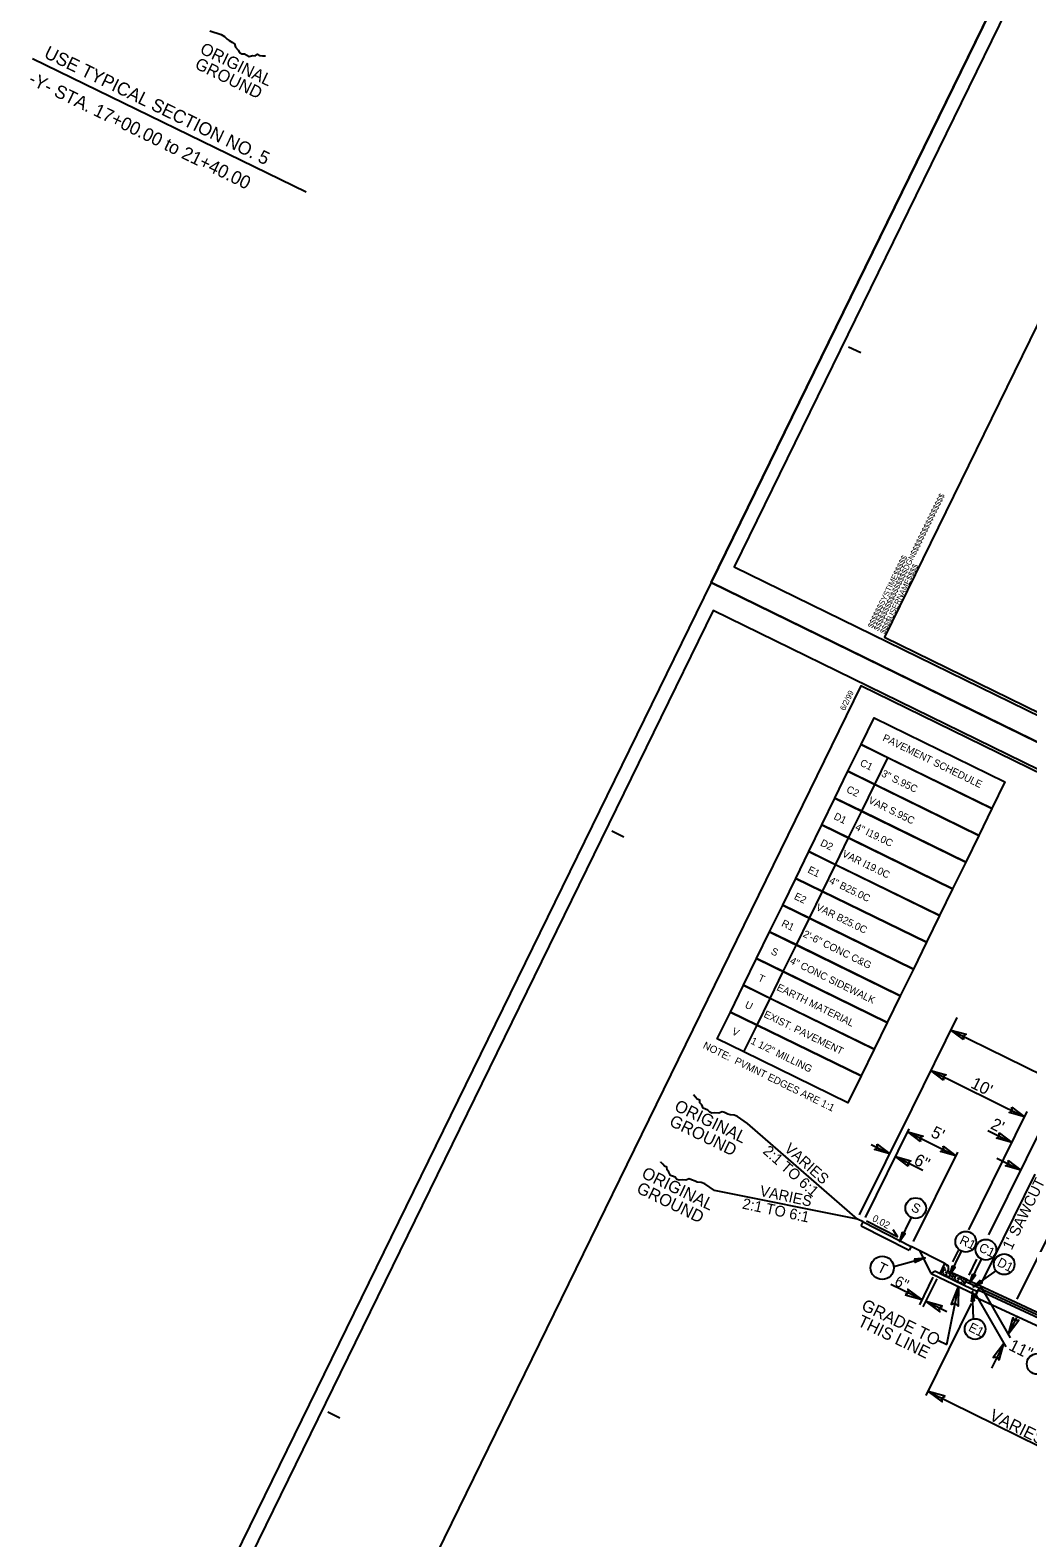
# Model space of a CAD drawing. Extents: x 1518247 to 1523638, y 635234 to 639927.
# Drawn here: x 1519327 to 1520253, y 636076 to 637475 of the extents above; entities that cross this region are included whole.
import ezdxf

# ---------------------------------------------------------------- set-up
doc = ezdxf.new("R2010")
doc.units = 0
for name, color, linetype in [('Default', 7, 'Continuous'), ('DTM TIN Hull White', 7, 'Continuous'), ('Old_Level_21', 7, 'Continuous'), ('Prop Dimension', 7, 'Continuous'), ('Prop Pavement Schedule Description CELL', 7, 'Continuous'), ('Prop Shade Light', 7, 'Continuous'), ('Sheet Cutting Line CELL', 7, 'Continuous'), ('Sheet Plot Border Inside CELL', 7, 'Continuous'), ('Sheet Plot Border Outside CELL', 7, 'Continuous'), ('Sheet Typical CELL', 7, 'Continuous'), ('Typical Berm CELL', 7, 'Continuous'), ('Typical Berm Information CELL', 7, 'Continuous'), ('Typical Curb CELL', 7, 'Continuous'), ('Typical Hinge Slope Arterial CELL', 7, 'Continuous'), ('Typical Hinge Slope Interstate CELL', 7, 'Continuous'), ('Typical ID Circle CELL', 7, 'Continuous'), ('Typical Pavement Slope CELL', 7, 'Continuous'), ('Typical Pavement Slope Information CELL', 7, 'Continuous'), ('Typical Shoulder Slope CELL', 7, 'Continuous'), ('Typical Text General CELL', 7, 'Continuous'), ('Typical Text ID Circle CELL', 7, 'Continuous'), ('Typical Text Label CELL', 7, 'Continuous')]:
    doc.layers.add(name, color=color, linetype=linetype)

# ---------------------------------------------------------------- blocks, each defined once
blk = doc.blocks.new('TERMINATOR')
at = {"layer": 'Prop Shade Light'}
blk.add_lwpolyline([(-0.469, 0.081), (0, 0), (-0.471, -0.083), (-0.411, 0)], close=True, dxfattribs=at)

msp = doc.modelspace()

# ---------------------------------------------------------------- linework, layer by layer
at = {"layer": 'Default'}
msp.add_lwpolyline([(1521471.5, 636222.3), (1519958.7, 636962.2), (1520442, 637950.3), (1521954.7, 637210.5)], close=True, dxfattribs=at)
at = {"layer": 'DTM TIN Hull White'}
for p, q in [((1520203.4, 636299.5), (1520206.5, 636306.1)), ((1520206.5, 636306.1), (1520445.2, 636195.2)), ((1520203.4, 636299.5), (1520442.1, 636188.9))]:
    msp.add_line(p, q, dxfattribs=at)
at = {"layer": 'Prop Dimension'}
for p, q in [((1520145.1, 636474), (1520186.9, 636558.6)), ((1520181.2, 636547), (1521070.1, 636107.9)), ((1520162.6, 636509.4), (1520249.4, 636466.5)), ((1520096.5, 636375.6), (1520145.1, 636474)), ((1520197.8, 636361.6), (1520252, 636471.5)), ((1520101.8, 636373), (1520142.5, 636455.5)), ((1520215.6, 636453.7), (1520237.8, 636442.7)), ((1520216.5, 636356.9), (1520269, 636463.2)), ((1520107.1, 636440.8), (1520124.5, 636432.2)), ((1520141.1, 636452.6), (1520185.9, 636430.4)), ((1520242.8, 636297.4), (1520313.8, 636441)), ((1520129.7, 636429.6), (1520155.1, 636417.1)), ((1520146.6, 636350.9), (1520187.5, 636433.8)), ((1520223.7, 636428.2), (1520246.2, 636417.1)), ((1520210.1, 636313.5), (1520259.5, 636413.3)), ((1520183, 636331.9), (1520188.3, 636342.5)), ((1520198, 636319.5), (1520205.4, 636334.5)), ((1520164.5, 636317.9), (1520151.9, 636292.1)), ((1520168, 636316.1), (1520155.3, 636290.2)), ((1520154.3, 636297), (1520125.6, 636311)), ((1520177.3, 636255.2), (1520188.3, 636309)), ((1520204.2, 636301.4), (1520232.2, 636253)), ((1520208.4, 636309.9), (1520236.3, 636261.5)), ((1520177.5, 636285.7), (1520157.8, 636295.3)), ((1520158.3, 636208.1), (1520200.4, 636293.2)), ((1520242.1, 636280.5), (1520234.4, 636264.8)), ((1520169.6, 636259.1), (1520177.3, 636255.2)), ((1520230.2, 636256.3), (1520219, 636233.3)), ((1520160.2, 636211.8), (1520395.9, 636095.4))]:
    msp.add_line(p, q, dxfattribs=at)
at = {"layer": 'Prop Pavement Schedule Description CELL'}
for points in [[(1520122.7, 636799.6), (1520097.9, 636811.8), (1520110, 636836.6), (1520231.3, 636777.3), (1520219.2, 636752.4), (1520122.7, 636799.6)], [(1520110.6, 636774.8), (1520085.7, 636787), (1520097.9, 636811.8), (1520219.2, 636752.4), (1520207, 636727.6), (1520110.6, 636774.8), (1520122.7, 636799.6)], [(1520098.4, 636750), (1520073.6, 636762.1), (1520085.7, 636787), (1520207, 636727.6), (1520194.9, 636702.8), (1520098.4, 636750), (1520110.6, 636774.8)], [(1520086.3, 636725.2), (1520061.5, 636737.3), (1520073.6, 636762.1), (1520194.9, 636702.8), (1520182.8, 636678), (1520086.3, 636725.2), (1520098.4, 636750)], [(1520074.2, 636700.4), (1520049.4, 636712.5), (1520061.5, 636737.3), (1520182.8, 636678), (1520170.6, 636653.2), (1520074.2, 636700.4), (1520086.3, 636725.2)], [(1520062, 636675.6), (1520037.2, 636687.7), (1520049.4, 636712.5), (1520170.6, 636653.2), (1520158.5, 636628.4), (1520062, 636675.6), (1520074.2, 636700.4)], [(1520049.9, 636650.8), (1520025.1, 636662.9), (1520037.2, 636687.7), (1520158.5, 636628.4), (1520146.4, 636603.6), (1520049.9, 636650.8), (1520062, 636675.6)], [(1520037.8, 636626), (1520013, 636638.1), (1520025.1, 636662.9), (1520146.4, 636603.6), (1520134.2, 636578.8), (1520037.8, 636626), (1520049.9, 636650.8)], [(1520025.6, 636601.2), (1520000.8, 636613.3), (1520013, 636638.1), (1520134.2, 636578.8), (1520122.1, 636554), (1520025.6, 636601.2), (1520037.8, 636626)], [(1520013.5, 636576.4), (1519988.7, 636588.5), (1520000.8, 636613.3), (1520122.1, 636554), (1520110, 636529.2), (1520013.5, 636576.4), (1520025.6, 636601.2)], [(1520001.4, 636551.6), (1519976.6, 636563.7), (1519988.7, 636588.5), (1520110, 636529.2), (1520097.8, 636504.4), (1520001.4, 636551.6), (1520013.5, 636576.4)], [(1519989.2, 636526.8), (1519964.4, 636538.9), (1519976.6, 636563.7), (1520097.8, 636504.4), (1520085.7, 636479.6), (1519989.2, 636526.8), (1520001.4, 636551.6)]]:
    msp.add_lwpolyline(points, dxfattribs=at)
at = {"layer": 'Prop Shade Light'}
for points in [[(1520136, 636359.6), (1520133.4, 636350.9), (1520138.8, 636358.3), (1520136.9, 636358)], [(1520147.2, 636334.8), (1520157.3, 636335.7), (1520148.1, 636331.4), (1520148.9, 636333.5)], [(1520182.5, 636328.4), (1520180, 636319.7), (1520185.3, 636327), (1520183.4, 636326.7)], [(1520201.1, 636321), (1520198.6, 636312.3), (1520203.9, 636319.7), (1520202, 636319.3)], [(1520208.3, 636315.1), (1520201.9, 636308.8), (1520210.2, 636312.6), (1520208.3, 636313.3)], [(1520203, 636295.6), (1520201.1, 636304.4), (1520199.9, 636295.4), (1520201.4, 636296.6)]]:
    msp.add_lwpolyline(points, close=True, dxfattribs=at)
at = {"layer": 'Sheet Cutting Line CELL'}
for p, q in [((1520442, 637950.3), (1519958.7, 636962.2)), ((1519958.7, 636962.2), (1519475.4, 635974)), ((1519958.7, 636962.2), (1521471.5, 636222.3)), ((1521471.5, 636222.3), (1519958.7, 636962.2))]:
    msp.add_line(p, q, dxfattribs=at)
at = {"layer": 'Sheet Plot Border Inside CELL'}
for points in [[(1521940.8, 637192.3), (1520443.8, 637924.5), (1519980.2, 636976.6), (1521477.3, 636244.5)], [(1521457.5, 636204.1), (1519960.5, 636936.3), (1519496.9, 635988.5), (1520994, 635256.3)]]:
    msp.add_lwpolyline(points, close=True, dxfattribs=at)
at = {"layer": 'Sheet Plot Border Outside CELL'}
for points in [[(1521954.7, 637210.5), (1520442, 637950.3), (1519958.7, 636962.2), (1521471.5, 636222.3)], [(1521471.5, 636222.3), (1519958.7, 636962.2), (1519475.4, 635974), (1520988.2, 635234.2)]]:
    msp.add_lwpolyline(points, close=True, dxfattribs=at)
at = {"layer": 'Sheet Typical CELL'}
for p, q in [((1520086.2, 637180.9), (1520097.5, 637175.4)), ((1520119.7, 636911.3), (1520119.7, 636911.3)), ((1520119.7, 636911.3), (1520119.7, 636911.3)), ((1520119.7, 636911.3), (1520119.7, 636911.3)), ((1520119.7, 636911.3), (1520119.7, 636911.3)), ((1520119.7, 636911.3), (1520119.7, 636911.3)), ((1520119.7, 636911.3), (1520119.7, 636911.3)), ((1519866.6, 636731.7), (1519877.8, 636726.2)), ((1520098, 636365.5), (1520099.8, 636369.1)), ((1520098, 636365.5), (1520142.5, 636342.8)), ((1520099.8, 636369.1), (1520144.3, 636346.3)), ((1520144.3, 636346.3), (1520142.5, 636342.8)), ((1519603, 636192.7), (1519614.2, 636187.3))]:
    msp.add_line(p, q, dxfattribs=at)
for points in [[(1521928.5, 637195.5), (1520581, 637854.5), (1520119.7, 636911.3), (1521467.2, 636252.3)], [(1521445.2, 636207.3), (1520097.7, 636866.4), (1519636.4, 635923.1), (1520983.9, 635264.1)]]:
    msp.add_lwpolyline(points, close=True, dxfattribs=at)
msp.add_lwpolyline([(1520153.4, 636894.8), (1520153.4, 636894.8)], dxfattribs=at)
at = {"layer": 'Typical Berm CELL'}
for p, q in [((1520099.8, 636369.1), (1520094.6, 636371.7)), ((1520175.5, 636330.3), (1520144.3, 636346.3))]:
    msp.add_line(p, q, dxfattribs=at)
at = {"layer": 'Typical Curb CELL'}
for p, q in [((1520171.1, 636321.3), (1520175.5, 636330.3)), ((1520175.5, 636330.3), (1520177.8, 636329.2)), ((1520171.1, 636321.3), (1520193.5, 636310.3)), ((1520173.9, 636323.3), (1520172.6, 636323.1)), ((1520172.6, 636323.1), (1520173.9, 636322)), ((1520173.9, 636322), (1520173.9, 636323.3)), ((1520175.2, 636325.7), (1520174.1, 636326.8)), ((1520174.1, 636326.8), (1520175.7, 636326.5)), ((1520175.7, 636326.5), (1520175.2, 636325.7)), ((1520178.8, 636325.9), (1520178.9, 636326)), ((1520196.1, 636315.6), (1520180, 636322.6)), ((1520180.8, 636320.6), (1520180, 636319.7)), ((1520180, 636319.7), (1520181, 636319.1)), ((1520181, 636319.1), (1520180.8, 636320.6)), ((1520185.1, 636317.9), (1520183.8, 636317.6)), ((1520183.8, 636317.6), (1520185.1, 636316.5)), ((1520185.1, 636316.5), (1520185.1, 636317.9)), ((1520192, 636315.1), (1520191.2, 636314.2)), ((1520191.2, 636314.2), (1520192.2, 636313.6)), ((1520192.2, 636313.6), (1520192, 636315.1)), ((1520193.5, 636310.3), (1520196.1, 636315.6))]:
    msp.add_line(p, q, dxfattribs=at)
for centre in [(1520175.1, 636329.3), (1520177.2, 636328.6), (1520172.6, 636321.1), (1520174.3, 636320.7), (1520174.4, 636324.5), (1520174.8, 636327.4), (1520175.6, 636319.4), (1520175.7, 636324.4), (1520176.6, 636322.2), (1520176.6, 636320.1), (1520177.3, 636318.9), (1520177.6, 636321.4), (1520178.1, 636323), (1520178.2, 636323.6), (1520179.2, 636318.2), (1520179.3, 636321.5), (1520180, 636322.3), (1520180.3, 636316.9), (1520181.6, 636321.1), (1520181.8, 636318.7), (1520182.3, 636316.1), (1520182.5, 636317.9), (1520182.6, 636321), (1520183.2, 636319.8), (1520183.6, 636318.9), (1520183.8, 636315.6), (1520183.9, 636319.9), (1520185.5, 636315.2), (1520185.6, 636319), (1520186.8, 636313.9), (1520186.9, 636319), (1520187.8, 636316.7), (1520187.8, 636314.7), (1520188.8, 636315.9), (1520189.3, 636317.6), (1520189.4, 636318.1), (1520190.5, 636316), (1520191.2, 636316.8), (1520192.8, 636315.6), (1520192.8, 636316.7), (1520194, 636315.9), (1520194.5, 636314.3), (1520195.1, 636314.4), (1520188.5, 636313.4), (1520190.4, 636312.7), (1520191.6, 636311.4), (1520193, 636313.2), (1520193.5, 636310.7), (1520193.7, 636312.4), (1520194.9, 636313.4)]:
    msp.add_circle(centre, 0.0802, dxfattribs=at)
for centre, start, end in [((1520176.7, 636327), 333.9377, 63.9377), ((1520181, 636324.8), 153.9377, 246.3222)]:
    msp.add_arc(centre, 2.4, start, end, dxfattribs=at)
at = {"layer": 'Typical Hinge Slope Interstate CELL'}
for p, q in [((1520094.6, 636371.7), (1519992.3, 636460.3)), ((1520094.6, 636371.7), (1519961.9, 636398.1)), ((1520162.8, 636321.2), (1520152.8, 636342)), ((1520167, 636323.3), (1520162.8, 636321.2)), ((1520207.4, 636307.9), (1520204.3, 636301.4))]:
    msp.add_line(p, q, dxfattribs=at)
for points in [[(1519493.5, 637473.8), (1519504.1, 637470.5), (1519507.1, 637468.7), (1519509.5, 637466), (1519511.5, 637464.8), (1519514.5, 637463.1), (1519516.5, 637461.9), (1519517.4, 637458.7), (1519519.8, 637455.9), (1519521.2, 637453.8), (1519523.2, 637452.6), (1519525.8, 637452.4), (1519527.8, 637451.2), (1519529.9, 637450.1), (1519533, 637450.9), (1519535.6, 637450.7), (1519537.8, 637452.2), (1519539.8, 637451), (1519542.4, 637450.8), (1519545, 637450.7), (1519545.2, 637450.6)], [(1519992.3, 636460.3), (1519983.3, 636466.7), (1519980, 636468), (1519976.4, 636468.2), (1519974.2, 636469.1), (1519971, 636470.4), (1519968.8, 636471.2), (1519965.8, 636469.9), (1519962.1, 636470.1), (1519959.5, 636469.9), (1519957.4, 636470.8), (1519955.6, 636472.7), (1519953.5, 636473.6), (1519951.3, 636474.5), (1519950, 636477.5), (1519948.3, 636479.4), (1519948.1, 636482), (1519945.9, 636482.9), (1519944.2, 636484.8), (1519942.5, 636486.8), (1519942.4, 636486.9)], [(1519961.9, 636398.1), (1519952.8, 636404.4), (1519949.6, 636405.7), (1519945.9, 636405.9), (1519943.8, 636406.8), (1519940.5, 636408.1), (1519938.4, 636409), (1519935.3, 636407.7), (1519931.7, 636407.9), (1519929.1, 636407.7), (1519926.9, 636408.5), (1519925.2, 636410.5), (1519923, 636411.4), (1519920.9, 636412.2), (1519919.6, 636415.2), (1519917.9, 636417.2), (1519917.6, 636419.8), (1519915.5, 636420.7), (1519913.8, 636422.6), (1519912, 636424.5), (1519911.9, 636424.7)]]:
    msp.add_lwpolyline(points, dxfattribs=at)
at = {"layer": 'Typical ID Circle CELL'}
for p, q in [((1520144.3, 636373.2), (1520133.4, 636350.9)), ((1520190.8, 636342), (1520180, 636319.7)), ((1520128.3, 636327.8), (1520157.4, 636335.7)), ((1520209.4, 636334.6), (1520198.6, 636312.3)), ((1520223.1, 636323.8), (1520202, 636308.8)), ((1520202.2, 636279.1), (1520201.1, 636303.8))]:
    msp.add_line(p, q, dxfattribs=at)
for centre, radius in [((1520148.5, 636381.8), 9.59), ((1520195, 636350.6), 9.59), ((1520213.7, 636343.2), 9.59), ((1520117.5, 636326.4), 10.8), ((1520230.6, 636329.7), 9.59), ((1520203.6, 636269.6), 9.59), ((1520261.2, 636237.3), 9.59)]:
    msp.add_circle(centre, radius, dxfattribs=at)
at = {"layer": 'Typical Pavement Slope CELL'}
for p, q in [((1520167, 636323.3), (1520171.1, 636321.3)), ((1520196.1, 636315.6), (1520241.4, 636294.5)), ((1520207.3, 636307.9), (1520472.1, 636185)), ((1520241.4, 636294.5), (1520350.2, 636244))]:
    msp.add_line(p, q, dxfattribs=at)
at = {"layer": 'Typical Pavement Slope Information CELL'}
for q in [(1520103, 636369.8), (1520127.7, 636361.8)]:
    msp.add_line((1520132.1, 636354.9), q, dxfattribs=at)
at = {"layer": 'Typical Shoulder Slope CELL'}
for p, q in [((1520162.8, 636321.2), (1520204.3, 636301.4)), ((1520193.5, 636310.3), (1520205.8, 636304.6)), ((1520195, 636313.6), (1520207.3, 636307.9))]:
    msp.add_line(p, q, dxfattribs=at)
at = {"layer": 'Typical Text Label CELL'}
msp.add_line((1519328.9, 637448.2), (1519582.9, 637324.6), dxfattribs=at)

# ---------------------------------------------------------------- block references
at = {"layer": 'Prop Dimension'}
for p, xscale, yscale, rotation in [((1520181.2, 636547), 30.9388560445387, 33.305184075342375, 153.71146049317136), ((1520162.6, 636509.4), 30.9388560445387, 33.305184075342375, 153.71146049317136), ((1520249.5, 636466.5), 30.9388560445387, 33.305184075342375, -26.28853950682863), ((1520141.1, 636452.6), 30.9388560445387, 33.305184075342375, 153.71146049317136), ((1520124.5, 636432.2), 30.9388560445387, 33.305184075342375, -26.28853950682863), ((1520237.8, 636442.7), 30.9388560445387, 33.305184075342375, -26.28853950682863), ((1520129.7, 636429.6), 30.9388560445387, 33.305184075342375, 153.71146049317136), ((1520185.9, 636430.4), 30.9388560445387, 33.305184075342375, -26.28853950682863), ((1520246.2, 636417.1), 30.9388560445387, 33.305184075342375, -26.28853950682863), ((1520154.3, 636297), 33.82820784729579, -36.41552511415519, -26.020730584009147), ((1520188.3, 636309), 38.04253472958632, 40.95218065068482, 78.30414461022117), ((1520157.8, 636295.3), 33.82820784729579, -36.41552511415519, 153.97926941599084), ((1520234.4, 636264.8), 33.82820784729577, -36.415525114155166, -115.99597801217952), ((1520230.2, 636256.3), 33.82820784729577, -36.41552511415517, 64.0796934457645), ((1520160.2, 636211.8), 33.82820784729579, -36.41552511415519, 153.97926941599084)]:
    msp.add_blockref('TERMINATOR', p, dxfattribs=dict(at, xscale=xscale, yscale=yscale, rotation=rotation))

# ---------------------------------------------------------------- texts
at = {"layer": 'Old_Level_21'}
msp.add_text('NOTE:  PVMNT EDGES ARE 1:1', height=6.75, rotation=333.8298, dxfattribs=at).set_placement((1519950.5, 636530.5))
at = {"layer": 'Prop Dimension'}
for s, height, rotation, p in [("10'", 11.19, 333.7115, (1520198.8, 636493.9)), ("5'", 11.19, 333.7115, (1520161.7, 636448.5)), ("2'", 11.19, 333.7115, (1520217.1, 636456)), ('6"', 11.19, 333.7115, (1520145.9, 636422.9)), ("1' SAWCUT", 10, 63.9377, (1520237.5, 636342.3)), ('6"', 9.97, 333.9793, (1520128, 636310.7)), ('11"', 11.19, 333.7115, (1520233.9, 636250.8)), ("VARIES 41' TO 24'", 11.189, 333.7115, (1520216, 636185.9))]:
    msp.add_text(s, height=height, rotation=rotation, dxfattribs=at).set_placement(p)
at = {"layer": 'Prop Pavement Schedule Description CELL'}
for s, p in [('PAVEMENT SCHEDULE', (1520117.2, 636815.8)), ('C1', (1520096.2, 636792.6)), ('3" S.95C', (1520116.1, 636782.7)), ('C2', (1520083.6, 636768)), ('VAR S.95C', (1520104, 636757.9)), ('D1', (1520071.9, 636743)), ('4" I19.0C', (1520091.8, 636733.1)), ('D2', (1520059.4, 636718.4)), ('VAR I19.0C', (1520079.7, 636708.3)), ('E1', (1520047.7, 636693.4)), ('4" B25.0C', (1520067.6, 636683.5)), ('E2', (1520035.1, 636668.8)), ('VAR B25.0C', (1520055.4, 636658.7)), ('R1', (1520023.4, 636643.8)), ('2\'-6" CONC C&G', (1520043.3, 636633.9)), ('S', (1520013.6, 636617.8)), ('4" CONC SIDEWALK', (1520031.2, 636609.1)), ('T', (1520001.5, 636593)), ('EARTH MATERIAL', (1520019, 636584.3)), ('U', (1519989.4, 636568.2)), ('EXIST. PAVEMENT', (1520006.9, 636559.4)), ('V', (1519977.3, 636543.4)), ('1 1/2" MILLING', (1519994.8, 636534.6))]:
    msp.add_text(s, height=6.75, rotation=333.9377, dxfattribs=at).set_placement(p)
at = {"layer": 'Sheet Typical CELL'}
for s, p in [('$$$$$$$$$$$$$$$$DGN$$$$$$$$$$$$$$$$', (1520113.9, 636916.8)), ('$$$$$$SYSTIME$$$$$', (1520108.4, 636919.4)), ('$$$$USERNAME$$$$', (1520119.8, 636913.9)), ('6/2/99', (1520082.7, 636842.8))]:
    msp.add_text(s, height=5.25, rotation=63.9377, dxfattribs=at).set_placement(p)
at = {"layer": 'Typical Berm Information CELL'}
msp.add_text('0.02', height=6.49, rotation=331.7597, dxfattribs=at).set_placement((1520107.6, 636370.3))
at = {"layer": 'Typical Hinge Slope Arterial CELL'}
for s, rotation, p in [('VARIES', 318.3038, (1520025.9, 636435.7)), ('2:1 TO 6:1', 318.3038, (1520006, 636433.5)), ('VARIES', 347.9774, (1520003.2, 636393.3)), ('2:1 TO 6:1', 347.9774, (1519987, 636381.5))]:
    msp.add_text(s, height=9.97, rotation=rotation, dxfattribs=at).set_placement(p)
at = {"layer": 'Typical Hinge Slope Interstate CELL'}
for s, p in [('ORIGINAL', (1519483.5, 637453.5)), ('GROUND', (1519478.8, 637439.5)), ('ORIGINAL', (1519923.7, 636472.9)), ('GROUND', (1519919, 636458.8)), ('ORIGINAL', (1519893.3, 636410.6)), ('GROUND', (1519888.6, 636396.6))]:
    msp.add_text(s, height=11.21, rotation=334.0511, dxfattribs=at).set_placement(p)
at = {"layer": 'Typical Pavement Slope CELL'}
msp.add_text('-Y- STA. 17+00.00 to 21+40.00', height=12.164, rotation=334.0511, dxfattribs=at).set_placement((1519324.4, 637425.3))
at = {"layer": 'Typical Text General CELL'}
for s, p in [('GRADE TO', (1520097.3, 636287.9)), ('THIS LINE', (1520093.8, 636273.2))]:
    msp.add_text(s, height=11.21, rotation=334.0511, dxfattribs=at).set_placement(p)
at = {"layer": 'Typical Text ID Circle CELL'}
for s, height, rotation, p in [('S', 8.58, 333.9793, (1520143.6, 636379.7)), ('R1', 8.58, 333.9793, (1520188.5, 636349.3)), ('C1', 8.58, 333.9793, (1520206.3, 636342.3)), ('T', 9.65, 333.6189, (1520112.1, 636323.6)), ('D1', 8.58, 333.2514, (1520223.3, 636328.7)), ('E1', 8.58, 333.2514, (1520196.7, 636268.4))]:
    msp.add_text(s, height=height, rotation=rotation, dxfattribs=at).set_placement(p)
at = {"layer": 'Typical Text Label CELL'}
msp.add_text('USE TYPICAL SECTION NO. 5', height=12.164, rotation=334.0511, dxfattribs=at).set_placement((1519338.8, 637449.5))

doc.saveas('drawing.dxf')
